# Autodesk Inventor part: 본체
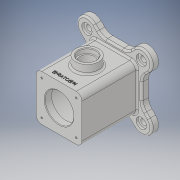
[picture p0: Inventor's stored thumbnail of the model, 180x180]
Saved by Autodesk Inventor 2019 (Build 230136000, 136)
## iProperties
Created: 2021-01
Part Number: 본체
Material: 일반
Document SubType Name: Modeling
Designer: 3DPRO16
Density: 1 g/cm^3
Appearance: 기본값
Mass: 385.865 g
Surface Area: 854.376 cm^2
Volume: 385.865 cm^3
Author: 3DPRO16
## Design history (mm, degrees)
sketch "스케치1"
  geometry: L1 (-40, -40)-(40, -40); L2 (40, -40)-(40, 40); L3 (40, 40)-(-40, 40); L4 (-40, 40)-(-40, -40); L5 (-40, -40)-(40, 40); L6 (40, -40)-(-40, 40); 1 further point
  constraints: 12 end point, 2 midpoint, 2 parallel, 1 horizontal, 1 perpendicular
  dimensions: "d0" = 80 distance of L3.end L2.end; "d1" = 80 distance of L2.end L1.end
extrude "돌출1" new body sketch "스케치1" stored distance "d2" = 96; taper "d3" = 0 deg
sketch "스케치3"
  geometry: C1 r 25 at (0, 0); 1 further point
  constraints: 1 centre point, 1 coincident
  dimensions: "d7" = 50 diameter of C1
extrude "돌출3" cut sketch "스케치3" distance "d8" = 12; taper "d9" = 0 deg
sketch "스케치4"
  geometry: L1 (-48, -48)-(48, -48); L2 (48, -48)-(48, 48); L3 (48, 48)-(-48, 48); L4 (-48, 48)-(-48, -48); L5 (-48, -48)-(48, 48); L6 (48, -48)-(-48, 48); 1 further point
  constraints: 12 end point, 2 midpoint, 2 parallel, 1 horizontal, 1 perpendicular
  dimensions: "d10" = 96 distance of L3.end L2.end; "d11" = 96 distance of L2.end L1.end
extrude "돌출4" join sketch "스케치4" distance "d12" = 12; taper "d13" = 0 deg
sketch "스케치5" dims "d36" = 134
  geometry: L1 (-48, 48)-(-48, -48) reference; L2 (48, 48)-(-48, 48) reference; L3 (-48, 48)-(-48, -48) reference; L4 (0, 0)-(-48, 48); L5 (-60.104, 34.648)-(-48, 22.544); L6 (-34.648, 60.104)-(-22.544, 48); A1 r 18 centre (-47.376, 47.376) between (-60.104, 34.648) and (-34.648, 60.104); 3 further points
  constraints: 6 end point, 5 point on line, 2 coincident, 2 parallel, 2 point on circle, 2 tangent, 1 centre point, 3 other
  dimensions: "d38" = 36 diameter of A1
sketch "스케치7"
  geometry: C1 r 35 at (0, 0); 1 further point
  constraints: 1 centre point, 1 coincident
  dimensions: "d30" = 70 diameter of C1
extrude "돌출6" cut sketch "스케치7" distance "d31" = 84; taper "d32" = 0 deg
sketch "스케치8"
  geometry: C1 r 25 at (0, 0); 1 further point
  constraints: 1 centre point, 1 coincident
  dimensions: "d33" = 50 diameter of C1
extrude "돌출7" cut sketch "스케치8" distance "d34" = 12; taper "d35" = 0 deg
extrude "돌출8" join sketch "스케치5" distance "d39" = 12; taper "d40" = 0 deg
sketch "스케치9"
  geometry: A1 r 18 centre (47.376, 47.376) between (60.104, 34.648) and (34.648, 60.104) reference; 2 further points
  constraints: 1 coincident
hole "구멍2" sketch "스케치9" at (47.376, 47.376) diameter "d41" = 10; stored, may be unused: countersink angle "d45" = 90 deg, drill point angle "d47" = 118 deg; dims "d42" = 6, "d43" = 18, "d44" = 4, "d46" = 26.75
sketch "스케치10"
  geometry: L1 (17.456, 96)-(62.544, 96) reference; C1 r 20 at (40, 49); 1 further point
  constraints: 1 centre point, 1 vertical alignment
  dimensions: "d93" = 40 diameter of C1; "d94" = 47 distance from line of L1 C1.centre
extrude "돌출9" join sketch "스케치10" distance "d52" = 15; taper "d53" = 0 deg
sketch "스케치12"
  geometry: L1 (80, 0)-(0, 0) reference; 2 further points
  constraints: 1 vertical alignment, 1 other
  dimensions: "d61" = 10 distance from line of L1 point (40, 10)
feature "엠보싱1" sketch "스케치12" dims "d0" = 80, "d1" = 80, "d62" = 0.5, "d63" = 0
fillet "모깎기1" dims "d64" = 10
sketch "스케치13"
  geometry: A1 r 10 centre (-30, 30) between (-30, 40) and (-40, 30) reference; 2 further points
  constraints: 1 coincident
hole "구멍4" sketch "스케치13" at (-30, 30) diameter "d65" = 3.242; stored, may be unused: countersink angle "d69" = 90 deg, drill point angle "d71" = 118 deg; dims "d66" = 8, "d67" = 30, "d68" = 8, "d70" = 10
sketch "스케치14"
  geometry: L1 (-30, -30)-(30, -30); L2 (30, -30)-(30, 30); L3 (30, 30)-(-30, 30); L4 (-30, 30)-(-30, -30); L5 (-30, -30)-(30, 30); L6 (30, -30)-(-30, 30); C1 r 1.621 at (30, 30) reference; C2 r 1.621 at (30, -30) reference; 5 further points
  constraints: 12 end point, 4 coincident, 2 midpoint, 2 parallel, 1 horizontal, 1 perpendicular
  dimensions: "d78" = 60 distance of L3.end L2.end (derived); "d79" = 60 distance of L2.end L1.end (derived)
hole "구멍5" sketch "스케치14" at (-30, 30), (30, 30), (30, -30), (-30, -30) diameter "d80" = 3.242; stored, may be unused: countersink angle "d84" = 90 deg, drill point angle "d86" = 118 deg; dims "d81" = 8, "d82" = 30, "d83" = 8, "d85" = 10
fillet "모깎기2" dims "d87" = 20
fillet "모깎기3" dims "d88" = 3
fillet "모깎기4" dims "d92" = 3
sketch "스케치15"
  geometry: C1 r 20 at (0, 0) reference; 2 further points
  constraints: 1 coincident
hole "구멍6" sketch "스케치15" at (0, 0) diameter "d95" = 25; stored, may be unused: countersink angle "d99" = 90 deg, drill point angle "d101" = 118 deg; dims "d96" = 6, "d97" = 30, "d98" = 8, "d100" = 45.25
chamfer "모따기2" distance "d102" = 1; stored, may be unused: second distance "d103" = 2, angle "d104" = 45 deg
fillet "모깎기5" dims "d105" = 3
node "솔리드1"
pattern_circular "원형 패턴3" dims angle "d49" = 360 deg
pattern_linear "직사각형 패턴1" dims "d74" = 60, "d77" = 60
